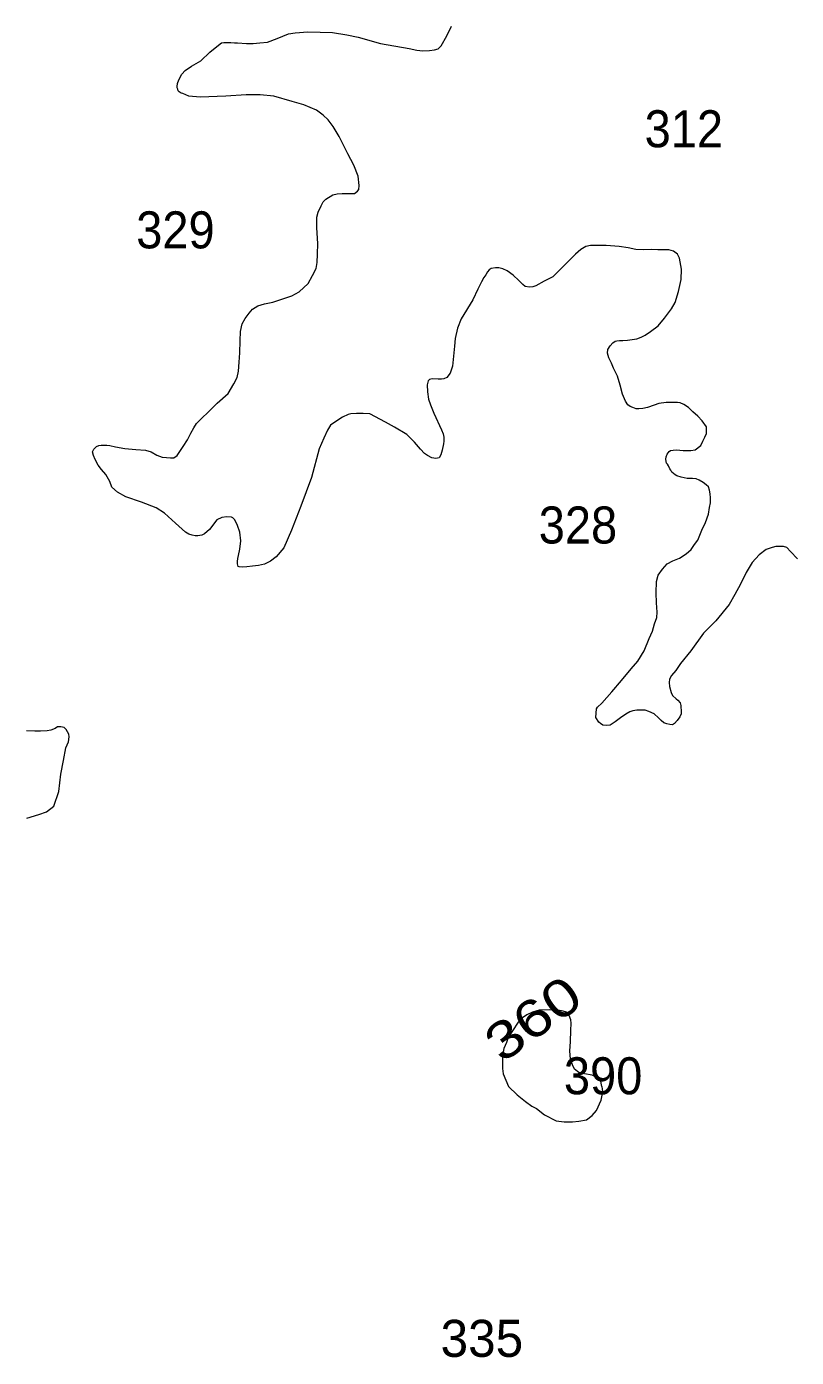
# Model space of a CAD drawing. Extents: x 445.4 to 500, y 8728.7 to 8784.
# Drawn here: x 445.41 to 448.74, y 8760.84 to 8766.59 of the extents above; entities that cross this region are included whole.
import ezdxf
from ezdxf.enums import TextEntityAlignment as Align

# ---------------------------------------------------------------- set-up
doc = ezdxf.new("R2010")
doc.units = 0
doc.header["$LTSCALE"] = 0.064
doc.layers.add('2', color=7, linetype='Continuous', lineweight=13)
doc.layers.add('21', color=7, linetype='Continuous')
doc.layers.add('61', color=7, linetype='Continuous')

msp = doc.modelspace()

# ---------------------------------------------------------------- linework, layer by layer
at = {"layer": '2'}
for points in [[(446.0629, 8766.3194), (446.0607, 8766.3259), (446.0607, 8766.3312), (446.0618, 8766.3441), (446.0672, 8766.3603), (446.0801, 8766.3839), (446.0951, 8766.4), (446.1221, 8766.4193), (446.1619, 8766.4419), (446.202, 8766.4799), (446.2386, 8766.5096), (446.2521, 8766.5191), (446.2616, 8766.5218), (446.2792, 8766.5218), (446.2914, 8766.5218), (446.3076, 8766.5204), (446.3212, 8766.5191), (446.3591, 8766.5164), (446.3889, 8766.5164), (446.4173, 8766.5191), (446.4512, 8766.5231), (446.4918, 8766.538), (446.5419, 8766.5583), (446.5704, 8766.5623), (446.6245, 8766.5677), (446.7315, 8766.5637), (446.7938, 8766.5542), (446.842, 8766.5436), (446.9382, 8766.5166), (447.0627, 8766.4949), (447.0952, 8766.4882), (447.1223, 8766.4855), (447.1508, 8766.4868), (447.1724, 8766.4895), (447.1887, 8766.4936), (447.2009, 8766.5071), (447.2252, 8766.5504), (447.2456, 8766.5922)], [(446.0962, 8764.4047), (446.0528, 8764.4439), (446.0052, 8764.4872), (445.9701, 8764.5099), (445.906, 8764.5347), (445.8378, 8764.5574), (445.8026, 8764.578), (445.7783, 8764.6003), (445.7692, 8764.6243), (445.752, 8764.6551), (445.7337, 8764.6767), (445.7189, 8764.695), (445.7052, 8764.72), (445.6983, 8764.736), (445.6949, 8764.752), (445.6995, 8764.7645), (445.712, 8764.7759), (445.7223, 8764.7793), (445.7315, 8764.7816), (445.7429, 8764.7816), (445.7566, 8764.7816), (445.7692, 8764.7793), (445.7934, 8764.7742), (445.8338, 8764.7673), (445.8821, 8764.7623), (445.9235, 8764.7594), (445.9482, 8764.7525), (445.9728, 8764.7387), (445.9955, 8764.7289), (446.0142, 8764.7279), (446.0309, 8764.7269), (446.0457, 8764.7269), (446.0595, 8764.7368), (446.0723, 8764.7535), (446.0861, 8764.7751), (446.1045, 8764.8036), (446.119, 8764.8332), (446.1318, 8764.8564), (446.1438, 8764.8748), (446.163, 8764.894), (446.1991, 8764.9276), (446.2337, 8764.9629), (446.28, 8765.0039), (446.3052, 8765.0462), (446.3197, 8765.0739), (446.325, 8765.1004), (446.3277, 8765.14), (446.3303, 8765.1797), (446.3318, 8765.2321), (446.3337, 8765.2731), (446.3414, 8765.3055), (446.3538, 8765.3284), (446.3719, 8765.3513), (446.3863, 8765.3685), (446.4092, 8765.3828), (446.4369, 8765.3923), (446.4742, 8765.399), (446.5076, 8765.4114), (446.5564, 8765.4266), (446.588, 8765.4432), (446.6256, 8765.4797), (446.6455, 8765.5151), (446.6611, 8765.5453), (446.6653, 8765.5703), (446.6664, 8765.6068), (446.6674, 8765.6527), (446.6642, 8765.7206), (446.6642, 8765.7661), (446.6695, 8765.7875), (446.682, 8765.8151), (446.691, 8765.8329), (446.7022, 8765.8435), (446.7325, 8765.863), (446.7521, 8765.8666), (446.7735, 8765.8684), (446.7949, 8765.8684), (446.8269, 8765.8684), (446.8394, 8765.879), (446.8447, 8765.8862), (446.8465, 8765.9039), (446.8429, 8765.943), (446.8234, 8765.991), (446.7984, 8766.0408), (446.7607, 8766.1157), (446.7337, 8766.1586), (446.7127, 8766.1865), (446.6917, 8766.2065), (446.6627, 8766.2284), (446.6081, 8766.2517), (446.5571, 8766.2657), (446.4782, 8766.2886), (446.4192, 8766.2956), (446.3582, 8766.2946), (446.2699, 8766.2887), (446.159, 8766.2847), (446.111, 8766.2897), (446.0844, 8766.3001), (446.0779, 8766.3022), (446.0693, 8766.3076), (446.065, 8766.3119), (446.0629, 8766.3194)], [(448.365, 8764.553), (448.364, 8764.5716), (448.3609, 8764.5872), (448.3557, 8764.6006), (448.3464, 8764.6099), (448.3329, 8764.6203), (448.3163, 8764.6296), (448.3028, 8764.6358), (448.2873, 8764.6368), (448.2645, 8764.6368), (448.2386, 8764.6427), (448.2189, 8764.649), (448.2116, 8764.6531), (448.1981, 8764.6645), (448.193, 8764.6727), (448.1888, 8764.679), (448.1836, 8764.6924), (448.1795, 8764.6986), (448.1753, 8764.7038), (448.1733, 8764.71), (448.1722, 8764.7203), (448.1733, 8764.7307), (448.1774, 8764.7421), (448.1857, 8764.7534), (448.1919, 8764.7586), (448.2033, 8764.7596), (448.2178, 8764.7607), (448.2468, 8764.7586), (448.2624, 8764.7586), (448.28, 8764.7586), (448.2987, 8764.7617), (448.3235, 8764.7803), (448.3318, 8764.7979), (448.3401, 8764.8165), (448.3474, 8764.831), (448.3484, 8764.8486), (448.3484, 8764.861), (448.3295, 8764.8865), (448.3098, 8764.9061), (448.2891, 8764.9258), (448.2704, 8764.9434), (448.2497, 8764.9568), (448.2341, 8764.9641), (448.2227, 8764.9661), (448.2072, 8764.9661), (448.173, 8764.9651), (448.1419, 8764.9609), (448.1211, 8764.9537), (448.0932, 8764.9434), (448.0724, 8764.9392), (448.0548, 8764.9382), (448.0434, 8764.9382), (448.0289, 8764.9434), (448.0185, 8764.9485), (448.0071, 8764.9558), (447.9978, 8764.9713), (447.9854, 8765.0023), (447.974, 8765.0406), (447.9626, 8765.0789), (447.9457, 8765.1138), (447.9369, 8765.1354), (447.9257, 8765.1593), (447.9201, 8765.1784), (447.9217, 8765.1952), (447.9321, 8765.2103), (447.9433, 8765.2231), (447.9529, 8765.2303), (447.9609, 8765.2327), (447.9713, 8765.2335), (447.9865, 8765.2335), (448.0057, 8765.2351), (448.0472, 8765.2406), (448.0656, 8765.2478), (448.0832, 8765.2566), (448.105, 8765.2721), (448.1387, 8765.297), (448.1666, 8765.3307), (448.1959, 8765.3702), (448.2121, 8765.398), (448.2263, 8765.4458), (448.2381, 8765.497), (448.2395, 8765.5424), (448.2307, 8765.5892), (448.2219, 8765.6068), (448.2058, 8765.6199), (448.1853, 8765.6258), (448.1677, 8765.6258), (448.1369, 8765.6258), (448.1105, 8765.6272), (448.0738, 8765.6258), (448.043, 8765.6272), (448.0093, 8765.6346), (447.9697, 8765.6404), (447.914, 8765.6433), (447.8459, 8765.6443), (447.8269, 8765.6399), (447.8049, 8765.6268), (447.7814, 8765.6063), (447.7374, 8765.5624), (447.6832, 8765.5082), (447.6465, 8765.4892)], [(447.6465, 8765.4892), (447.6098, 8765.4702), (447.5966, 8765.4658), (447.5834, 8765.4643), (447.5644, 8765.4672), (447.5541, 8765.476), (447.5365, 8765.4921), (447.5116, 8765.5155), (447.4867, 8765.5345), (447.4676, 8765.5433), (447.45, 8765.5477), (447.4353, 8765.5477), (447.4177, 8765.5448), (447.4089, 8765.5389), (447.4016, 8765.5302), (447.3943, 8765.517), (447.3855, 8765.5053), (447.3752, 8765.4863), (447.3591, 8765.4555), (447.3385, 8765.4087), (447.2869, 8765.3272), (447.2722, 8765.2862), (447.262, 8765.2423), (447.259, 8765.2087), (447.2502, 8765.1223), (447.24, 8765.093), (447.2253, 8765.074), (447.2121, 8765.0682), (447.2018, 8765.0667), (447.1886, 8765.0667), (447.1622, 8765.0682), (447.1505, 8765.0652), (447.1446, 8765.0594), (447.1402, 8765.0418), (447.1416, 8765.0114), (447.146, 8764.9807), (447.1548, 8764.9558), (447.1695, 8764.9192), (447.2032, 8764.8475), (447.2091, 8764.83), (447.212, 8764.8153), (447.212, 8764.7992), (447.2106, 8764.7875), (447.2047, 8764.7597), (447.2003, 8764.7392), (447.193, 8764.726), (447.1783, 8764.7231), (447.1607, 8764.726), (447.1416, 8764.7363), (447.1284, 8764.7451), (447.1123, 8764.7641), (447.0859, 8764.7948), (447.0522, 8764.827), (446.9994, 8764.8592), (446.9598, 8764.8812), (446.8923, 8764.9163), (446.8645, 8764.9178), (446.8352, 8764.9178), (446.8102, 8764.9163), (446.7985, 8764.9134), (446.775, 8764.9017), (446.7457, 8764.8841), (446.7222, 8764.868), (446.7105, 8764.8461), (446.6944, 8764.8109), (446.6739, 8764.7656), (446.6408, 8764.6415), (446.5939, 8764.5171), (446.5543, 8764.4146), (446.5205, 8764.337), (446.4883, 8764.299), (446.4633, 8764.28), (446.4369, 8764.2668), (446.412, 8764.2609), (446.3856, 8764.258), (446.3607, 8764.2551), (446.3416, 8764.2536), (446.3284, 8764.2551), (446.324, 8764.2565), (446.3211, 8764.2682), (446.3211, 8764.2785), (446.3226, 8764.2917), (446.3255, 8764.3048), (446.3314, 8764.3312), (446.3358, 8764.3678), (446.3314, 8764.4058), (446.3211, 8764.4336), (446.3094, 8764.4585), (446.3006, 8764.4673), (446.2947, 8764.4702), (446.2742, 8764.4717), (446.2536, 8764.4688), (446.2317, 8764.4585), (446.1996, 8764.4171), (446.1789, 8764.3985), (446.1665, 8764.3923), (446.1499, 8764.3902), (446.1375, 8764.3902), (446.1251, 8764.3923), (446.1107, 8764.3964), (446.0962, 8764.4047)], [(448.7405, 8764.2906), (448.7107, 8764.3217), (448.6944, 8764.3393), (448.6809, 8764.3434), (448.6632, 8764.3434), (448.647, 8764.3434), (448.632, 8764.3393), (448.6063, 8764.3299), (448.5751, 8764.3069), (448.5453, 8764.2744), (448.5195, 8764.2311), (448.4951, 8764.181), (448.4707, 8764.1363), (448.446, 8764.0934), (448.3877, 8764.0217), (448.3348, 8763.9689), (448.2806, 8763.8931), (448.2353, 8763.838), (448.215, 8763.8083), (448.196, 8763.7866), (448.1879, 8763.7704), (448.1865, 8763.7555), (448.1879, 8763.7379), (448.1947, 8763.7122), (448.2014, 8763.7), (448.2164, 8763.6851), (448.2245, 8763.6797), (448.234, 8763.6675), (448.2367, 8763.6567), (448.2367, 8763.6472), (448.2381, 8763.6364), (448.2381, 8763.6201), (448.2326, 8763.608), (448.2204, 8763.5917), (448.2096, 8763.5782), (448.2014, 8763.5728), (448.1892, 8763.5741), (448.1757, 8763.5768), (448.1635, 8763.5809), (448.1513, 8763.5917), (448.1404, 8763.6025), (448.1214, 8763.6201), (448.0984, 8763.631), (448.0821, 8763.6364), (448.074, 8763.6364), (448.0469, 8763.6364), (448.0292, 8763.6337), (448.0157, 8763.6283), (447.9994, 8763.6188), (447.9764, 8763.6025), (447.9533, 8763.5863), (447.9316, 8763.5714), (447.9153, 8763.5701), (447.8991, 8763.5714), (447.8896, 8763.5782), (447.8828, 8763.585), (447.8693, 8763.6039), (447.8706, 8763.6228), (447.8718, 8763.6422), (447.8772, 8763.649), (447.8949, 8763.6666), (447.9382, 8763.7153), (447.9803, 8763.764), (448.0223, 8763.8141), (448.0508, 8763.8479), (448.0779, 8763.8926), (448.1005, 8763.9463), (448.114, 8763.9773), (448.1233, 8764.0094), (448.1327, 8764.0363), (448.1347, 8764.0591), (448.1316, 8764.0994), (448.1296, 8764.1429), (448.1316, 8764.1915), (448.1389, 8764.2192), (448.1575, 8764.2461), (448.1783, 8764.2688), (448.2021, 8764.2812), (448.2311, 8764.2937), (448.2602, 8764.3112), (448.2819, 8764.3309), (448.2954, 8764.3516), (448.3099, 8764.3702), (448.3277, 8764.4134), (448.3432, 8764.4465), (448.3567, 8764.4827), (448.3609, 8764.5116), (448.365, 8764.5323), (448.365, 8764.553)], [(445.4101, 8763.1691), (445.4628, 8763.1859), (445.4961, 8763.197), (445.5266, 8763.2219), (445.5488, 8763.2855), (445.5571, 8763.3603), (445.5682, 8763.4184), (445.5793, 8763.4738), (445.59, 8763.5), (445.5936, 8763.5208), (445.5924, 8763.533), (445.5802, 8763.5525), (445.5716, 8763.5611), (445.5569, 8763.5635), (445.5435, 8763.5635), (445.5325, 8763.5574), (445.5141, 8763.5501), (445.4983, 8763.5464), (445.4701, 8763.5452), (445.4457, 8763.5452), (445.4095, 8763.5462)]]:
    msp.add_lwpolyline(points, dxfattribs=at)
msp.add_lwpolyline([(447.6134, 8761.9148), (447.6473, 8761.8873), (447.6982, 8761.8619), (447.7321, 8761.8577), (447.7682, 8761.8577), (447.7957, 8761.8598), (447.8297, 8761.8661), (447.853, 8761.8852), (447.8721, 8761.9063), (447.8721, 8761.9063), (447.8932, 8761.9508), (447.8932, 8761.9508), (447.8996, 8761.9868), (447.8975, 8762.0102), (447.8954, 8762.0102), (447.889, 8762.0397), (447.889, 8762.0397), (447.889, 8762.0397), (447.853, 8762.0587), (447.853, 8762.0587), (447.8211, 8762.0651), (447.8211, 8762.0651), (447.7966, 8762.0712), (447.7776, 8762.0843), (447.768, 8762.1042), (447.7606, 8762.1298), (447.7577, 8762.1628), (447.7599, 8762.2039), (447.7612, 8762.2526), (447.7623, 8762.2843), (447.7612, 8762.2984), (447.7541, 8762.3172), (447.7541, 8762.3172), (447.7423, 8762.3312), (447.7283, 8762.3359), (447.7047, 8762.3406), (447.6683, 8762.3418), (447.6248, 8762.3406), (447.5954, 8762.3312), (447.5707, 8762.3195), (447.5531, 8762.3066), (447.5343, 8762.2876), (447.5087, 8762.2512), (447.4905, 8762.222), (447.4832, 8762.2002), (447.4722, 8762.1746), (447.4667, 8762.1418), (447.4667, 8762.1127), (447.4667, 8762.0872), (447.4686, 8762.0653), (447.4686, 8762.0653), (447.4923, 8762.0102), (447.5288, 8761.9741), (447.5654, 8761.945), (447.5928, 8761.9249)], close=True, dxfattribs=at)

# ---------------------------------------------------------------- texts
at = {"layer": '21', "width": 0.95}
for s, p in [('312', (448.0802, 8766.0684)), ('329', (445.8831, 8765.6316)), ('328', (447.6226, 8764.3563)), ('390', (447.7314, 8761.9764))]:
    msp.add_text(s, height=0.16, dxfattribs=at).set_placement(p)
at = {"layer": '21'}
msp.add_text('335', height=0.16, dxfattribs=at).set_placement((447.1985, 8760.8419))
at = {"layer": '61', "width": 1.25}
msp.add_text('360', height=0.16, rotation=36.035, dxfattribs=at).set_placement((447.6449, 8762.239), align=Align.CENTER)

doc.saveas('drawing.dxf')
